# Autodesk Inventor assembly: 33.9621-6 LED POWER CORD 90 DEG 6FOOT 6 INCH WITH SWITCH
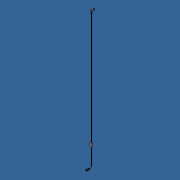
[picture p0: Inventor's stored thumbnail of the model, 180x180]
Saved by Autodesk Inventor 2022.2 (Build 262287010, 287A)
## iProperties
Created: 2018-05
Part Number: 33.9621-6 LED POWER CORD 90 DEG 6FOOT 6 INCH WITH SWITCH
Document SubType Name: Assembly
Designer: amoles
Author: amoles
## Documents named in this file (4)
- L:\INVENTOR LIBRARIES\PARTS LIBRARY\WORKSTATION\LIGHTS OUTWATER PLASTICS\33.9621-6 LED POWER CORD 90 DEG 6FOOT 6 INCH WITH SWITCH.iam
- L:\INVENTOR LIBRARIES\PARTS LIBRARY\WORKSTATION\LIGHTS OUTWATER PLASTICS\SUBCOMPONENTS\33.9621 PLUG WITH ROCKER ARM.ipt
- L:\INVENTOR LIBRARIES\PARTS LIBRARY\WORKSTATION\LIGHTS OUTWATER PLASTICS\SUBCOMPONENTS\33.9621 CORD BENT SHEET METAL.ipt
- L:\INVENTOR LIBRARIES\PARTS LIBRARY\WORKSTATION\LIGHTS OUTWATER PLASTICS\SUBCOMPONENTS\33.9621 PLUG END 90 DEG.ipt
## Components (3 placed, 3 different names)
1. 33.9621 PLUG WITH ROCKER ARM:1 — Mate:1, Mate:2, Mate:3
2. 33.9621 CORD BENT SHEET METAL:1 — Mate:1, Mate:2, Mate:3, Mate:4, Mate:5, Mate:6
3. 33.9621 PLUG END 90 DEG:1 — Mate:4, Mate:5, Mate:6
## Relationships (6: Mate 6)
- Mate:1: 33.9621 PLUG WITH ROCKER ARM:1 ↔ 33.9621 CORD BENT SHEET METAL:1
- Mate:2: 33.9621 PLUG WITH ROCKER ARM:1 ↔ 33.9621 CORD BENT SHEET METAL:1
- Mate:3: 33.9621 PLUG WITH ROCKER ARM:1 ↔ 33.9621 CORD BENT SHEET METAL:1
- Mate:4: 33.9621 CORD BENT SHEET METAL:1 ↔ 33.9621 PLUG END 90 DEG:1
- Mate:5: 33.9621 CORD BENT SHEET METAL:1 ↔ 33.9621 PLUG END 90 DEG:1
- Mate:6: 33.9621 CORD BENT SHEET METAL:1 ↔ 33.9621 PLUG END 90 DEG:1
